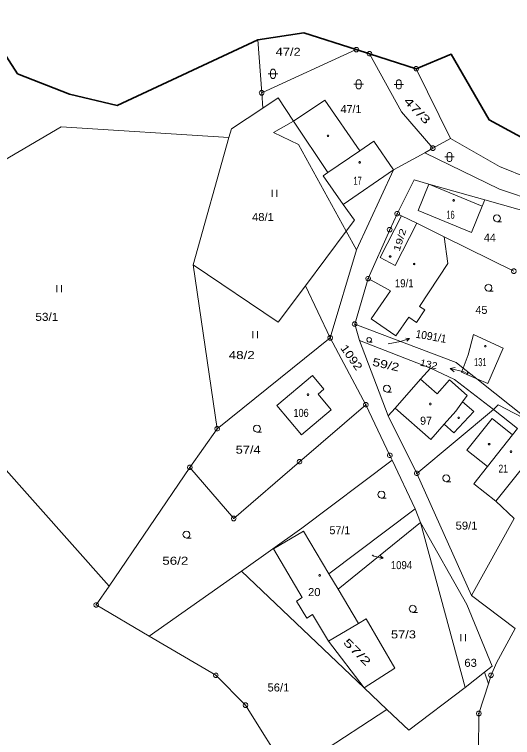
# Model space of a CAD drawing. Extents: x -687390 to -684106, y -954833 to -951648.
# Drawn here: x -687064.8 to -686959.1, y -952527.1 to -952373.7 of the extents above; entities that cross this region are included whole.
import ezdxf
from ezdxf.enums import TextEntityAlignment as Align

# ---------------------------------------------------------------- set-up
doc = ezdxf.new("R2010")
doc.units = 0
doc.header["$LTSCALE"] = 0.68
doc.header["$PDMODE"] = 32
doc.header["$PDSIZE"] = 0.34
for name, color, linetype, lineweight in [('1', 7, 'Continuous', 13), ('3', 7, 'Continuous', 13), ('4', 7, 'Continuous', 13), ('5', 7, 'Continuous', 13), ('7', 7, 'Continuous', 13), ('8', 7, 'Continuous', 13)]:
    doc.layers.add(name, color=color, linetype=linetype, lineweight=lineweight)
doc.layers.add('2', color=7, linetype='Continuous')

msp = doc.modelspace()

# ---------------------------------------------------------------- linework, layer by layer
at = {"layer": '1', "lineweight": 35}
for p, q in [((-687003.37, -952377.58), (-687013.17, -952379.01)), ((-687003.37, -952377.58), (-686992.25, -952381.12)), ((-687043.01, -952392.96), (-687013.17, -952379.01))]:
    msp.add_line(p, q, dxfattribs=at)
at = {"layer": '1'}
for p, q in [((-687013.17, -952379.01), (-687012.35, -952390.31)), ((-687012.35, -952390.31), (-686992.25, -952381.12)), ((-686979.52, -952385.17), (-686972.27, -952399.95)), ((-687012.35, -952390.31), (-687012.11, -952393.53)), ((-687008.82, -952391.36), (-687012.11, -952393.53)), ((-687005.61, -952396.3), (-687008.82, -952391.36)), ((-686998.92, -952391.82), (-687005.61, -952396.3)), ((-686998.92, -952391.82), (-686991.47, -952402.6)), ((-687012.11, -952393.53), (-687018.77, -952397.96)), ((-687005.61, -952396.3), (-687009.83, -952398.74)), ((-687054.93, -952397.52), (-687078.55, -952411.32)), ((-687054.93, -952397.52), (-687019.29, -952399.77)), ((-687004.5, -952401.24), (-687009.83, -952398.74)), ((-686976.01, -952402.05), (-686972.27, -952399.95)), ((-686972.27, -952399.95), (-686961.85, -952405.92)), ((-686977.69, -952403), (-686984.37, -952406.6)), ((-686977.69, -952403), (-686976.01, -952402.05)), ((-686977.69, -952403), (-686961.84, -952410.74)), ((-686936.96, -952416.03), (-686961.85, -952405.92)), ((-686984.37, -952406.6), (-686992.23, -952423.61)), ((-686965.54, -952414.32), (-686964.98, -952412.98)), ((-686983.58, -952415.95), (-686982.66, -952416.4)), ((-686974.05, -952420.64), (-686979.43, -952417.99)), ((-686972.85, -952426.55), (-686973.6, -952420.87)), ((-686997.79, -952442.3), (-686992.23, -952423.61)), ((-687104.75, -952427.63), (-687044.76, -952494.97)), ((-687026.93, -952426.83), (-687008.83, -952439)), ((-686978.8, -952435.67), (-686972.85, -952426.55)), ((-686989.73, -952429.72), (-686985.02, -952432.3)), ((-687003.06, -952431.26), (-687008.83, -952439)), ((-687003.06, -952431.26), (-686997.79, -952442.3)), ((-686985.02, -952432.3), (-686989.08, -952438.25)), ((-686977.71, -952436.38), (-686978.8, -952435.67)), ((-686967.35, -952441.62), (-686968.47, -952445.93)), ((-686997.79, -952442.3), (-686990.24, -952456.5)), ((-686991.59, -952442.87), (-686985.48, -952458.85)), ((-686971.08, -952447.5), (-686969.58, -952448.7)), ((-686978.61, -952451.08), (-686976.5, -952448.76)), ((-686976.5, -952448.76), (-686971.4, -952451.14)), ((-686969.58, -952448.7), (-686966.69, -952451)), ((-687009.14, -952456.69), (-687001.59, -952450.3)), ((-686984.01, -952457.19), (-686978.61, -952451.08)), ((-686963.14, -952457.5), (-686971.4, -952451.14)), ((-686955.32, -952460.02), (-686966.69, -952451)), ((-687009.14, -952456.69), (-687003.9, -952462.88)), ((-686990.24, -952456.5), (-687004.3, -952468.61)), ((-686990.24, -952456.5), (-686985.12, -952467.25)), ((-686962.16, -952456.52), (-686963.14, -952457.5)), ((-686984.01, -952457.19), (-686985.48, -952458.85)), ((-686968.75, -952466.13), (-686964.4, -952469.63)), ((-687018.28, -952480.65), (-687004.3, -952468.61)), ((-687003.83, -952482.72), (-686984.63, -952468.28)), ((-687027.6, -952469.8), (-687044.76, -952494.97)), ((-686964.4, -952469.63), (-686967.29, -952473.25)), ((-686979.4, -952471.06), (-686967.78, -952496.96)), ((-686962.65, -952476.97), (-686967.29, -952473.25)), ((-686958.75, -952480.67), (-686962.65, -952476.97)), ((-686979.74, -952478.58), (-686998.06, -952492.41)), ((-686979.74, -952478.58), (-686978.62, -952481.47)), ((-686978.62, -952481.47), (-686996.13, -952495.65)), ((-686968.81, -952498.9), (-686978.62, -952481.47)), ((-686998.06, -952492.41), (-687003.47, -952483.32)), ((-687044.76, -952494.97), (-687047.49, -952499)), ((-686968.81, -952498.9), (-686963.4, -952512)), ((-686990.18, -952501.95), (-686991.81, -952502.92)), ((-686990.18, -952501.95), (-686984.09, -952512.44)), ((-686958.55, -952503.97), (-686962.48, -952511.27)), ((-686998.17, -952506.7), (-686990.57, -952516.59)), ((-686965.03, -952513.28), (-686963.4, -952512)), ((-686963.64, -952513.93), (-686962.48, -952511.27)), ((-686984.09, -952512.44), (-686990.57, -952516.59)), ((-686965.03, -952513.28), (-686964.21, -952515.71)), ((-686964.21, -952515.71), (-686963.64, -952513.93)), ((-686969.12, -952516.5), (-686981.13, -952525.56)), ((-687006.67, -952534.81), (-686985.77, -952521.15)), ((-686985.77, -952521.15), (-686981.13, -952525.56))]:
    msp.add_line(p, q, dxfattribs=at)
at = {"layer": '1', "lineweight": 35}
for points in [[(-687098.29, -952347.95), (-687092.6, -952348.56), (-687078.11, -952357.72), (-687073.06, -952372.61), (-687064.2, -952386.23), (-687053.17, -952390.55), (-687043.01, -952392.96)], [(-686992.25, -952381.12), (-686989.46, -952382.01), (-686979.52, -952385.17)], [(-686979.52, -952385.17), (-686972.11, -952382.05), (-686964.06, -952396.03), (-686952.3, -952402.38)]]:
    msp.add_lwpolyline(points, dxfattribs=at)
at = {"layer": '1'}
for points in [[(-686989.46, -952382.01), (-686982.67, -952394.31), (-686976.01, -952402.05)], [(-687018.77, -952397.96), (-687019.29, -952399.77), (-687026.93, -952426.83)], [(-686992.23, -952423.61), (-686994.38, -952419.67), (-687004.5, -952401.24)], [(-686984.37, -952406.6), (-686988.52, -952400.56), (-686991.47, -952402.6)], [(-686983.58, -952415.95), (-686980, -952408.77), (-686976.83, -952409.66), (-686979.09, -952415.24), (-686967.82, -952419.92), (-686965.54, -952414.32)], [(-686976.83, -952409.66), (-686964.98, -952412.98), (-686954.68, -952415.87)], [(-686954.68, -952415.87), (-686953.83, -952413.41), (-686961.84, -952410.74)], [(-686983.58, -952415.95), (-686985.16, -952419.34), (-686989.73, -952429.72), (-686992.59, -952439.39), (-686971.08, -952447.5)], [(-686958.81, -952428.15), (-686973.6, -952420.87), (-686974.05, -952420.64)], [(-686997.79, -952442.3), (-687021.81, -952461.6), (-687026.93, -952426.83)], [(-686989.08, -952438.25), (-686983.84, -952441.85), (-686981.11, -952437.91), (-686979.45, -952439.04), (-686977.71, -952436.38)], [(-686992.59, -952439.39), (-686991.59, -952442.87), (-686976.5, -952448.76)], [(-686967.35, -952441.62), (-686961.09, -952444.49), (-686964.33, -952451.99), (-686966.69, -952451), (-686969.95, -952449.61)], [(-686969.95, -952449.61), (-686969.58, -952448.7), (-686968.47, -952445.93)], [(-687003.9, -952462.88), (-686997.56, -952457.59), (-687000.38, -952454.24), (-686999.12, -952453.19), (-687001.59, -952450.3)], [(-686939.21, -952468.92), (-686955.32, -952460.02), (-686962.16, -952456.52)], [(-686963.14, -952457.5), (-686979.4, -952471.06), (-686985.48, -952458.85)], [(-686963.14, -952457.5), (-686957.99, -952461.53), (-686959.09, -952462.9)], [(-686959.09, -952462.9), (-686963.42, -952459.43), (-686968.75, -952466.13)], [(-687021.81, -952461.6), (-687027.6, -952469.8), (-687018.28, -952480.65)], [(-686985.12, -952467.25), (-686984.63, -952468.28), (-686979.74, -952478.58)], [(-686965.03, -952513.28), (-686969.12, -952516.5), (-686978.62, -952481.47)], [(-686958.75, -952480.67), (-686967.78, -952496.96), (-686958.55, -952503.97)], [(-687036.27, -952505.6), (-687016.6, -952491.83), (-687003.83, -952482.72)], [(-687001.57, -952501.05), (-687002.77, -952501.78), (-687004.93, -952498.17), (-687003.75, -952497.44), (-687009.83, -952487.1), (-687003.47, -952483.32)], [(-686985.77, -952521.15), (-686990.57, -952516.59), (-687016.6, -952491.83)], [(-686991.81, -952502.92), (-686996.13, -952495.65), (-686998.06, -952492.41)], [(-687022.1, -952513.92), (-687036.27, -952505.6), (-687047.49, -952499)], [(-686991.81, -952502.92), (-686998.17, -952506.7), (-687001.57, -952501.05)], [(-687006.67, -952534.81), (-687015.79, -952520.28), (-687022.1, -952513.92)], [(-687002.39, -952541.61), (-686984.71, -952559.53), (-686977.54, -952551.02), (-686969.71, -952537.55), (-686966.27, -952530.08), (-686966.24, -952522.04), (-686964.21, -952515.71)]]:
    msp.add_lwpolyline(points, dxfattribs=at)
msp.add_lwpolyline([(-686979.43, -952417.99), (-686982.66, -952416.4), (-686987.18, -952425.26), (-686983.99, -952426.92)], close=True, dxfattribs=at)
at = {"layer": '3'}
for p, q in [((-687010.1, -952410.9), (-687010.1, -952412.4)), ((-687009.1, -952412.4), (-687009.1, -952410.9)), ((-687055.86, -952431.13), (-687055.86, -952432.63)), ((-687054.86, -952432.63), (-687054.86, -952431.13)), ((-687014.25, -952440.85), (-687014.25, -952442.35)), ((-687013.25, -952442.35), (-687013.25, -952440.85)), ((-686970.08, -952505.17), (-686970.08, -952506.67)), ((-686969.08, -952506.67), (-686969.08, -952505.17))]:
    msp.add_line(p, q, dxfattribs=at)
for points in [[(-687010.95, -952386.25), (-687009.68, -952386.25), (-687008.95, -952386.25)], [(-686992.76, -952388.48), (-686991.49, -952388.48), (-686990.76, -952388.48)], [(-686984.22, -952388.5), (-686982.95, -952388.5), (-686982.22, -952388.5)], [(-686973.46, -952403.9), (-686972.19, -952403.9), (-686971.46, -952403.9)], [(-686962.39, -952417.65), (-686962.77, -952417.55), (-686963.04, -952417.28), (-686963.14, -952416.91), (-686963.04, -952416.54), (-686962.77, -952416.27), (-686962.4, -952416.17), (-686962.03, -952416.27), (-686961.76, -952416.54), (-686961.66, -952416.92), (-686961.76, -952417.3), (-686962.03, -952417.57), (-686962.41, -952417.67), (-686961.41, -952417.67)], [(-686964.19, -952432.39), (-686964.57, -952432.29), (-686964.84, -952432.02), (-686964.94, -952431.65), (-686964.84, -952431.28), (-686964.57, -952431.01), (-686964.2, -952430.91), (-686963.83, -952431.01), (-686963.56, -952431.28), (-686963.46, -952431.66), (-686963.56, -952432.04), (-686963.83, -952432.31), (-686964.21, -952432.41), (-686963.21, -952432.41)], [(-686989.52, -952443.19), (-686989.775, -952443.123), (-686989.956, -952442.942), (-686990.022, -952442.694), (-686989.956, -952442.446), (-686989.775, -952442.265), (-686989.527, -952442.198), (-686989.279, -952442.265), (-686989.098, -952442.446), (-686989.031, -952442.701), (-686989.098, -952442.955), (-686989.279, -952443.136), (-686989.533, -952443.203), (-686988.863, -952443.203)], [(-686985.75, -952453.81), (-686986.13, -952453.71), (-686986.4, -952453.44), (-686986.5, -952453.07), (-686986.4, -952452.7), (-686986.13, -952452.43), (-686985.76, -952452.33), (-686985.39, -952452.43), (-686985.12, -952452.7), (-686985.02, -952453.08), (-686985.12, -952453.46), (-686985.39, -952453.73), (-686985.77, -952453.83), (-686984.77, -952453.83)], [(-687013.34, -952462.31), (-687013.72, -952462.21), (-687013.99, -952461.94), (-687014.09, -952461.57), (-687013.99, -952461.2), (-687013.72, -952460.93), (-687013.35, -952460.83), (-687012.98, -952460.93), (-687012.71, -952461.2), (-687012.61, -952461.58), (-687012.71, -952461.96), (-687012.98, -952462.23), (-687013.36, -952462.33), (-687012.36, -952462.33)], [(-686973.15, -952472.82), (-686973.53, -952472.72), (-686973.8, -952472.45), (-686973.9, -952472.08), (-686973.8, -952471.71), (-686973.53, -952471.44), (-686973.16, -952471.34), (-686972.79, -952471.44), (-686972.52, -952471.71), (-686972.42, -952472.09), (-686972.52, -952472.47), (-686972.79, -952472.74), (-686973.17, -952472.84), (-686972.17, -952472.84)], [(-686986.92, -952476.31), (-686987.3, -952476.21), (-686987.57, -952475.94), (-686987.67, -952475.57), (-686987.57, -952475.2), (-686987.3, -952474.93), (-686986.93, -952474.83), (-686986.56, -952474.93), (-686986.29, -952475.2), (-686986.19, -952475.58), (-686986.29, -952475.96), (-686986.56, -952476.23), (-686986.94, -952476.33), (-686985.94, -952476.33)], [(-687028.31, -952484.79), (-687028.69, -952484.69), (-687028.96, -952484.42), (-687029.06, -952484.05), (-687028.96, -952483.68), (-687028.69, -952483.41), (-687028.32, -952483.31), (-687027.95, -952483.41), (-687027.68, -952483.68), (-687027.58, -952484.06), (-687027.68, -952484.44), (-687027.95, -952484.71), (-687028.33, -952484.81), (-687027.33, -952484.81)], [(-686980.27, -952500.55), (-686980.65, -952500.45), (-686980.92, -952500.18), (-686981.02, -952499.81), (-686980.92, -952499.44), (-686980.65, -952499.17), (-686980.28, -952499.07), (-686979.91, -952499.17), (-686979.64, -952499.44), (-686979.54, -952499.82), (-686979.64, -952500.2), (-686979.91, -952500.47), (-686980.29, -952500.57), (-686979.29, -952500.57)]]:
    msp.add_lwpolyline(points, dxfattribs=at)
for points in [[(-687010.45, -952385.75), (-687010.35, -952385.46), (-687010.1, -952385.28), (-687009.79, -952385.28), (-687009.54, -952385.46), (-687009.44, -952385.75), (-687009.44, -952386.75), (-687009.54, -952387.04), (-687009.79, -952387.22), (-687010.1, -952387.22), (-687010.35, -952387.04), (-687010.45, -952386.75)], [(-686992.26, -952387.98), (-686992.16, -952387.69), (-686991.91, -952387.51), (-686991.6, -952387.51), (-686991.35, -952387.69), (-686991.25, -952387.98), (-686991.25, -952388.98), (-686991.35, -952389.27), (-686991.6, -952389.45), (-686991.91, -952389.45), (-686992.16, -952389.27), (-686992.26, -952388.98)], [(-686983.72, -952388), (-686983.62, -952387.71), (-686983.37, -952387.53), (-686983.06, -952387.53), (-686982.81, -952387.71), (-686982.71, -952388), (-686982.71, -952389), (-686982.81, -952389.29), (-686983.06, -952389.47), (-686983.37, -952389.47), (-686983.62, -952389.29), (-686983.72, -952389)], [(-686972.96, -952403.4), (-686972.86, -952403.11), (-686972.61, -952402.93), (-686972.3, -952402.93), (-686972.05, -952403.11), (-686971.95, -952403.4), (-686971.95, -952404.4), (-686972.05, -952404.69), (-686972.3, -952404.87), (-686972.61, -952404.87), (-686972.86, -952404.69), (-686972.96, -952404.4)]]:
    msp.add_lwpolyline(points, close=True, dxfattribs=at)
msp.add_point((-686979.97, -952426.64), dxfattribs=at)
at = {"layer": '4'}
for p, q in [((-686965.54, -952414.32), (-686976.83, -952409.66)), ((-686992.61, -952417.29), (-686995.07, -952413.98)), ((-686971.09, -952457.83), (-686969.69, -952455.88)), ((-686984.01, -952457.19), (-686976.45, -952463.87)), ((-686971.09, -952457.83), (-686973.58, -952460.63)), ((-686976.45, -952463.87), (-686973.58, -952460.63)), ((-686971.55, -952462.48), (-686973.58, -952460.63)), ((-686964.4, -952469.63), (-686959.09, -952462.9)), ((-686962.65, -952476.97), (-686952.87, -952464.74))]:
    msp.add_line(p, q, dxfattribs=at)
for points in [[(-687005.61, -952396.3), (-686998.29, -952407.2), (-686991.47, -952402.6)], [(-686984.37, -952406.6), (-686995.07, -952413.98), (-686999.28, -952407.88), (-686998.29, -952407.2)], [(-686992.61, -952417.29), (-686994.38, -952419.67), (-687003.06, -952431.26)], [(-686978.61, -952451.08), (-686975.1, -952454.2), (-686972.47, -952451.24), (-686968.73, -952454.56)], [(-686968.73, -952454.56), (-686969.69, -952455.88), (-686967.29, -952457.95), (-686971.55, -952462.48)]]:
    msp.add_lwpolyline(points, dxfattribs=at)
at = {"layer": '5'}
for points in [[(-686998.16, -952399.28), (-686998.07, -952399.43), (-686998.16, -952399.58), (-686998.34, -952399.58), (-686998.43, -952399.43), (-686998.34, -952399.28)], [(-686991.42, -952404.9), (-686991.33, -952405.05), (-686991.42, -952405.2), (-686991.6, -952405.2), (-686991.69, -952405.05), (-686991.6, -952404.9)], [(-686971.52, -952412.96), (-686971.43, -952413.11), (-686971.52, -952413.26), (-686971.7, -952413.26), (-686971.79, -952413.11), (-686971.7, -952412.96)], [(-686984.97, -952424.9), (-686984.88, -952425.05), (-686984.97, -952425.2), (-686985.15, -952425.2), (-686985.24, -952425.05), (-686985.15, -952424.9)], [(-686964.75, -952443.93), (-686964.66, -952444.08), (-686964.75, -952444.23), (-686964.93, -952444.23), (-686965.02, -952444.08), (-686964.93, -952443.93)], [(-686968.6, -952449.73), (-686968.539, -952449.83), (-686968.6, -952449.93), (-686968.72, -952449.93), (-686968.781, -952449.83), (-686968.72, -952449.73)], [(-687002.42, -952454.21), (-687002.33, -952454.36), (-687002.42, -952454.51), (-687002.6, -952454.51), (-687002.69, -952454.36), (-687002.6, -952454.21)], [(-686976.46, -952456.19), (-686976.37, -952456.34), (-686976.46, -952456.49), (-686976.64, -952456.49), (-686976.73, -952456.34), (-686976.64, -952456.19)], [(-686970.43, -952459.12), (-686970.34, -952459.27), (-686970.43, -952459.42), (-686970.61, -952459.42), (-686970.7, -952459.27), (-686970.61, -952459.12)], [(-686963.95, -952464.73), (-686963.86, -952464.88), (-686963.95, -952465.03), (-686964.13, -952465.03), (-686964.22, -952464.88), (-686964.13, -952464.73)], [(-686959.3, -952466.31), (-686959.21, -952466.46), (-686959.3, -952466.61), (-686959.48, -952466.61), (-686959.57, -952466.46), (-686959.48, -952466.31)], [(-686999.93, -952492.56), (-686999.84, -952492.71), (-686999.93, -952492.86), (-687000.11, -952492.86), (-687000.2, -952492.71), (-687000.11, -952492.56)]]:
    msp.add_lwpolyline(points, close=True, dxfattribs=at)
at = {"layer": '7'}
for p, q in [((-686985.5, -952443.58), (-686982.89, -952443.09)), ((-686980.984, -952442.451), (-686982.89, -952443.09)), ((-686972.319, -952448.818), (-686969.4, -952449.51)), ((-686969.08, -952449.64), (-686969.4, -952449.51)), ((-686988.91, -952488.45), (-686988.51, -952488.61)), ((-686986.553, -952489.069), (-686988.51, -952488.61))]:
    msp.add_line(p, q, dxfattribs=at)
for points in [[(-686981.726, -952442.346), (-686980.984, -952442.451), (-686981.513, -952442.982)], [(-686971.461, -952449.535), (-686972.319, -952448.818), (-686971.231, -952448.562)], [(-686987.129, -952488.59), (-686986.553, -952489.069), (-686987.282, -952489.242)]]:
    msp.add_lwpolyline(points, dxfattribs=at)
at = {"layer": '8'}
for p, q in [((-686992.37, -952381.12), (-686992.13, -952381.12)), ((-686989.58, -952382.01), (-686989.34, -952382.01)), ((-686979.64, -952385.17), (-686979.4, -952385.17)), ((-687012.47, -952390.31), (-687012.23, -952390.31)), ((-686976.13, -952402.05), (-686975.89, -952402.05)), ((-686983.7, -952415.95), (-686983.46, -952415.95)), ((-686985.28, -952419.34), (-686985.04, -952419.34)), ((-686989.85, -952429.72), (-686989.61, -952429.72)), ((-686992.71, -952439.39), (-686992.47, -952439.39)), ((-686997.91, -952442.3), (-686997.67, -952442.3)), ((-686990.36, -952456.5), (-686990.12, -952456.5)), ((-687021.93, -952461.6), (-687021.69, -952461.6)), ((-686985.24, -952467.25), (-686985, -952467.25)), ((-687004.42, -952468.61), (-687004.18, -952468.61)), ((-687027.72, -952469.8), (-687027.48, -952469.8)), ((-686979.52, -952471.06), (-686979.28, -952471.06)), ((-687018.4, -952480.65), (-687018.16, -952480.65)), ((-687047.61, -952499), (-687047.37, -952499)), ((-687022.22, -952513.92), (-687021.98, -952513.92)), ((-686963.76, -952513.93), (-686963.52, -952513.93)), ((-687015.91, -952520.28), (-687015.67, -952520.28)), ((-686966.36, -952522.04), (-686966.12, -952522.04))]:
    msp.add_line(p, q, dxfattribs=at)
for points in [[(-686992.1, -952380.64), (-686991.85, -952380.82), (-686991.75, -952381.11), (-686991.85, -952381.4), (-686992.1, -952381.58), (-686992.41, -952381.58), (-686992.66, -952381.4), (-686992.76, -952381.11), (-686992.66, -952380.82), (-686992.41, -952380.64)], [(-686989.31, -952381.53), (-686989.06, -952381.71), (-686988.96, -952382), (-686989.06, -952382.29), (-686989.31, -952382.47), (-686989.62, -952382.47), (-686989.87, -952382.29), (-686989.97, -952382), (-686989.87, -952381.71), (-686989.62, -952381.53)], [(-686979.37, -952384.69), (-686979.12, -952384.87), (-686979.02, -952385.16), (-686979.12, -952385.45), (-686979.37, -952385.63), (-686979.68, -952385.63), (-686979.93, -952385.45), (-686980.03, -952385.16), (-686979.93, -952384.87), (-686979.68, -952384.69)], [(-687012.2, -952389.83), (-687011.95, -952390.01), (-687011.85, -952390.3), (-687011.95, -952390.59), (-687012.2, -952390.77), (-687012.51, -952390.77), (-687012.76, -952390.59), (-687012.86, -952390.3), (-687012.76, -952390.01), (-687012.51, -952389.83)], [(-686975.86, -952401.57), (-686975.61, -952401.75), (-686975.51, -952402.04), (-686975.61, -952402.33), (-686975.86, -952402.51), (-686976.17, -952402.51), (-686976.42, -952402.33), (-686976.52, -952402.04), (-686976.42, -952401.75), (-686976.17, -952401.57)], [(-686983.43, -952415.47), (-686983.18, -952415.65), (-686983.08, -952415.94), (-686983.18, -952416.23), (-686983.43, -952416.41), (-686983.74, -952416.41), (-686983.99, -952416.23), (-686984.09, -952415.94), (-686983.99, -952415.65), (-686983.74, -952415.47)], [(-686985.01, -952418.86), (-686984.76, -952419.04), (-686984.66, -952419.33), (-686984.76, -952419.62), (-686985.01, -952419.8), (-686985.32, -952419.8), (-686985.57, -952419.62), (-686985.67, -952419.33), (-686985.57, -952419.04), (-686985.32, -952418.86)], [(-686958.66, -952427.67), (-686958.41, -952427.85), (-686958.31, -952428.14), (-686958.41, -952428.43), (-686958.66, -952428.61), (-686958.97, -952428.61), (-686959.22, -952428.43), (-686959.32, -952428.14), (-686959.22, -952427.85), (-686958.97, -952427.67)], [(-686989.58, -952429.24), (-686989.33, -952429.42), (-686989.23, -952429.71), (-686989.33, -952430), (-686989.58, -952430.18), (-686989.89, -952430.18), (-686990.14, -952430), (-686990.24, -952429.71), (-686990.14, -952429.42), (-686989.89, -952429.24)], [(-686992.44, -952438.91), (-686992.19, -952439.09), (-686992.09, -952439.38), (-686992.19, -952439.67), (-686992.44, -952439.85), (-686992.75, -952439.85), (-686993, -952439.67), (-686993.1, -952439.38), (-686993, -952439.09), (-686992.75, -952438.91)], [(-686997.64, -952441.82), (-686997.39, -952442), (-686997.29, -952442.29), (-686997.39, -952442.58), (-686997.64, -952442.76), (-686997.95, -952442.76), (-686998.2, -952442.58), (-686998.3, -952442.29), (-686998.2, -952442), (-686997.95, -952441.82)], [(-686990.09, -952456.02), (-686989.84, -952456.2), (-686989.74, -952456.49), (-686989.84, -952456.78), (-686990.09, -952456.96), (-686990.4, -952456.96), (-686990.65, -952456.78), (-686990.75, -952456.49), (-686990.65, -952456.2), (-686990.4, -952456.02)], [(-687021.66, -952461.12), (-687021.41, -952461.3), (-687021.31, -952461.59), (-687021.41, -952461.88), (-687021.66, -952462.06), (-687021.97, -952462.06), (-687022.22, -952461.88), (-687022.32, -952461.59), (-687022.22, -952461.3), (-687021.97, -952461.12)], [(-686984.97, -952466.77), (-686984.72, -952466.95), (-686984.62, -952467.24), (-686984.72, -952467.53), (-686984.97, -952467.71), (-686985.28, -952467.71), (-686985.53, -952467.53), (-686985.63, -952467.24), (-686985.53, -952466.95), (-686985.28, -952466.77)], [(-687004.15, -952468.13), (-687003.9, -952468.31), (-687003.8, -952468.6), (-687003.9, -952468.89), (-687004.15, -952469.07), (-687004.46, -952469.07), (-687004.71, -952468.89), (-687004.81, -952468.6), (-687004.71, -952468.31), (-687004.46, -952468.13)], [(-687027.45, -952469.32), (-687027.2, -952469.5), (-687027.1, -952469.79), (-687027.2, -952470.08), (-687027.45, -952470.26), (-687027.76, -952470.26), (-687028.01, -952470.08), (-687028.11, -952469.79), (-687028.01, -952469.5), (-687027.76, -952469.32)], [(-686979.25, -952470.58), (-686979, -952470.76), (-686978.9, -952471.05), (-686979, -952471.34), (-686979.25, -952471.52), (-686979.56, -952471.52), (-686979.81, -952471.34), (-686979.91, -952471.05), (-686979.81, -952470.76), (-686979.56, -952470.58)], [(-687018.13, -952480.17), (-687017.88, -952480.35), (-687017.78, -952480.64), (-687017.88, -952480.93), (-687018.13, -952481.11), (-687018.44, -952481.11), (-687018.69, -952480.93), (-687018.79, -952480.64), (-687018.69, -952480.35), (-687018.44, -952480.17)], [(-687047.34, -952498.52), (-687047.09, -952498.7), (-687046.99, -952498.99), (-687047.09, -952499.28), (-687047.34, -952499.46), (-687047.65, -952499.46), (-687047.9, -952499.28), (-687048, -952498.99), (-687047.9, -952498.7), (-687047.65, -952498.52)], [(-687021.95, -952513.44), (-687021.7, -952513.62), (-687021.6, -952513.91), (-687021.7, -952514.2), (-687021.95, -952514.38), (-687022.26, -952514.38), (-687022.51, -952514.2), (-687022.61, -952513.91), (-687022.51, -952513.62), (-687022.26, -952513.44)], [(-686963.49, -952513.45), (-686963.24, -952513.63), (-686963.14, -952513.92), (-686963.24, -952514.21), (-686963.49, -952514.39), (-686963.8, -952514.39), (-686964.05, -952514.21), (-686964.15, -952513.92), (-686964.05, -952513.63), (-686963.8, -952513.45)], [(-687015.64, -952519.8), (-687015.39, -952519.98), (-687015.29, -952520.27), (-687015.39, -952520.56), (-687015.64, -952520.74), (-687015.95, -952520.74), (-687016.2, -952520.56), (-687016.3, -952520.27), (-687016.2, -952519.98), (-687015.95, -952519.8)], [(-686966.09, -952521.56), (-686965.84, -952521.74), (-686965.74, -952522.03), (-686965.84, -952522.32), (-686966.09, -952522.5), (-686966.4, -952522.5), (-686966.65, -952522.32), (-686966.75, -952522.03), (-686966.65, -952521.74), (-686966.4, -952521.56)]]:
    msp.add_lwpolyline(points, close=True, dxfattribs=at)

# ---------------------------------------------------------------- texts
at = {"layer": '2'}
for s, height, width, p in [('47/2', 1.7, 1.2, (-687009.375, -952382.43)), ('17', 1.7, 0.7, (-686992.875, -952409.81)), ('16', 1.7, 0.7, (-686973.145, -952417.02)), ('48/1', 1.7, 1.05, (-687014.405, -952417.5)), ('19/1', 1.7, 0.9, (-686984.065, -952431.56)), ('53/1', 1.7, 1.1, (-687060.405, -952438.69)), ('1091/1', 0.1, 0.9, (-686985.454, -952443.58)), ('48/2', 1.7, 1.25, (-687019.345, -952446.8)), ('131', 1.7, 0.7, (-686967.265, -952448.3)), ('132', 0.1, 0.9, (-686969.034, -952449.64)), ('106', 1.7, 0.85, (-687005.595, -952459.07)), ('57/4', 1.7, 1.2, (-687017.875, -952466.88)), ('21', 1.7, 0.8, (-686962.075, -952470.91)), ('59/1', 1.7, 1.05, (-686971.165, -952483)), ('56/2', 1.7, 1.25, (-687033.455, -952490.46)), ('1094', 0.1, 0.9, (-686988.864, -952488.45)), ('20', 1.7, 1.05, (-687002.505, -952497.11)), ('57/3', 1.7, 1.2, (-686984.895, -952506.09)), ('63', 1.7, 1.05, (-686969.306, -952512.13)), ('56/1', 1.7, 1.05, (-687011.115, -952517.36))]:
    msp.add_text(s, height=height, dxfattribs=dict(at, width=width)).set_placement(p)
for s, height, rotation, width, p in [('47/3', 1.7, 314.095, 1.55, (-686982.31, -952392.161)), ('19/2', 1.4, 72.307, 1.35, (-686983.093, -952424.054)), ('1092', 1.7, 305.444, 1.2, (-686995.715, -952444.47)), ('59/2', 1.7, 347.327, 1.3, (-686988.967, -952448.174)), ('57/2', 1.7, 315.012, 1.6, (-686995.164, -952507.086))]:
    msp.add_text(s, height=height, rotation=rotation, dxfattribs=dict(at, width=width)).set_placement(p)
for s, p in [('47/1', (-686995.595, -952394.58)), ('44', (-686965.155, -952421.86)), ('45', (-686966.945, -952437.21)), ('97', (-686978.705, -952460.74)), ('57/1', (-686997.955, -952483.98))]:
    msp.add_text(s, height=1.7, dxfattribs=at).set_placement(p)
at = {"layer": '7', "width": 0.95}
msp.add_text('1091/1', height=1.7, rotation=349.963, dxfattribs=at).set_placement((-686979.767, -952442.237))
at = {"layer": '7', "width": 1.2}
msp.add_text('132', height=1.4, rotation=347.098, dxfattribs=at).set_placement((-686975.197, -952448.983), align=Align.RIGHT)
at = {"layer": '7', "width": 0.9}
msp.add_text('1094', height=1.7, dxfattribs=at).set_placement((-686984.935, -952491.39))

doc.saveas('drawing.dxf')
